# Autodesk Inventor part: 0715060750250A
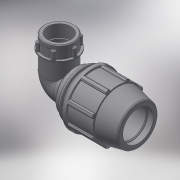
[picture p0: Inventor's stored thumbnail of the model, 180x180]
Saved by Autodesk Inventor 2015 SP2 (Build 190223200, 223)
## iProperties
Created: 2017-02
Part Number: 0715060750250A
Material: Generic
Description: PLASSON 90° ELBOW FEMALE ADAPTOR 75-2.1/2"
Document SubType Name: Modeling
Designer: KIM
Mass: 1287.77 g
Surface Area: 1760.4 cm^2
Volume: 1287.77 cm^3
Density: 1 g/cm^3
Appearance: Default
Author: KIM
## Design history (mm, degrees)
derived "87150.ipt"
feature "Solid1::87150.ipt"
tag "TaggingFeature1"
body "Solid1"
other parameters: "d2" = 75, "d4" = 15.91667, "d5" = 47.75, "d7" = 134, "d9" = 27.28571, "d11" = 6.36667, "d13" = 120 deg, "d14" = 97.5, "d15" = 12 deg, "d16" = 116.58, "d18" = 3.75, "d19" = 35 deg, "d20" = 17.5 deg, "d21" = 124.62, "d23" = 0, "d25" = 360 deg, "d27" = 2.68, "d33" = 1.5, "d42" = 70.67, "d43" = 4.02, "d46" = 2.25, "d51" = 191, "d68" = 12.73333, "d72" = 105, "d73" = 93.8938, "d74" = 36, "d75" = 107.97787, "d76" = 72.226, "d77" = 39.6, "d79" = 28.8904, "d80" = 2.16678, "d83" = 0, "d84" = 0, "d91" = 100.5, "d93" = 132, "d94" = 72.226, "d95" = 50.5582, "d96" = 12.73333, "d97" = 50 deg, "d98" = 65.0034, "d99" = 0.5, "d100" = 0.5, "d101" = 12, "d102" = 93.8938, "d103" = 30.96, "d104" = 0, "d108" = 360 deg, "d110" = 2.81681, "d111" = 8.93333, "d112" = 0, "d113" = 3.18333, "d114" = 3.18333, "d115" = 113.0826, "d_" = 75, "E_" = 134, "A_" = 191, "l_" = 132, "l_2" = 36, "A_1" = 105, "Rp_" = 72.226, "d105" = 14.08407
